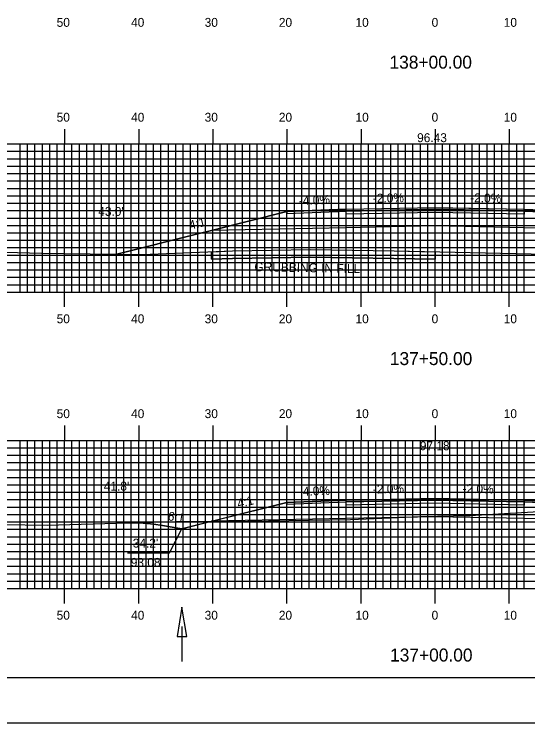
# Model space of a CAD drawing. Extents: x 1775564 to 1775907, y 442591 to 442811.
# Drawn here: x 1775672.9 to 1775742.2, y 442590.5 to 442686.2 of the extents above; entities that cross this region are included whole.
import ezdxf

# ---------------------------------------------------------------- set-up
doc = ezdxf.new("R2010")
doc.units = 0
for name, color, linetype in [('ANNOTATION', 7, 'Continuous'), ('BORDER', 7, 'Continuous'), ('D_Drainage_Ditch_Line', 7, 'Continuous'), ('D_Roadway_Centerline', 7, 'Continuous'), ('D_Roadway_Centerline_Text', 7, 'Continuous'), ('D_Roadway_Edge_Shoulder', 7, 'Continuous'), ('D_Roadway_Edge_TW', 7, 'Continuous'), ('D_Roadway_Pavement', 7, 'Continuous'), ('D_Roadway_SlopeLines', 7, 'Continuous'), ('D_Roadway_SubGrade', 7, 'Continuous'), ('D_Text_Standard', 7, 'Continuous'), ('GRUBBING IN FILL', 7, 'Continuous'), ('H_V ANNOTATION', 7, 'Continuous'), ('MAJOR', 7, 'Continuous'), ('MINOR', 7, 'Continuous'), ('PLOT BOUNDARY', 7, 'Continuous'), ('S_Roadway_Centerline', 7, 'Continuous')]:
    doc.layers.add(name, color=color, linetype=linetype)

msp = doc.modelspace()

# ---------------------------------------------------------------- linework, layer by layer
at = {"layer": 'ANNOTATION'}
msp.add_lwpolyline([(1775688.177, 442613.47), (1775693.869, 442613.47), (1775695.538, 442616.74)], dxfattribs=at)
at = {"layer": 'BORDER'}
msp.add_lwpolyline([(1775580.111, 442596.665), (1775900.111, 442596.665), (1775900.111, 442806.665), (1775580.111, 442806.665)], close=True, dxfattribs=at)
at = {"layer": 'D_Drainage_Ditch_Line'}
msp.add_line((1775695.538, 442603.524), (1775695.538, 442598.825), dxfattribs=at)
msp.add_lwpolyline([(1775694.882, 442602.211), (1775696.194, 442602.211), (1775695.538, 442606.148)], close=True, dxfattribs=at)
at = {"layer": 'D_Roadway_Centerline'}
for points in [[(1775686.739, 442653.791), (1775686.741, 442653.791), (1775697.711, 442656.534), (1775699.538, 442656.99), (1775705.211, 442658.409), (1775709.711, 442659.534), (1775717.712, 442659.854), (1775729.711, 442660.094), (1775731.768, 442660.053), (1775741.712, 442659.854), (1775747.545, 442659.621), (1775757.832, 442659.209), (1775757.833, 442659.209), (1775767.301, 442656.842), (1775774.243, 442655.106)], [(1775687.941, 442617.525), (1775688.446, 442617.526), (1775689.192, 442617.527), (1775690.297, 442617.476), (1775690.442, 442617.469), (1775691.691, 442617.351), (1775692.631, 442617.217), (1775692.942, 442617.173), (1775695.538, 442616.74), (1775699.537, 442617.74), (1775707.011, 442619.609), (1775709.711, 442620.284), (1775717.712, 442620.604), (1775722.433, 442620.699), (1775729.712, 442620.844), (1775739.526, 442620.648), (1775741.711, 442620.604), (1775753.997, 442620.112)]]:
    msp.add_lwpolyline(points, dxfattribs=at)
at = {"layer": 'D_Roadway_Edge_Shoulder'}
for points in [[(1775717.712, 442659.854), (1775709.711, 442659.534), (1775709.711, 442659.284), (1775717.712, 442659.604)], [(1775741.712, 442659.854), (1775757.833, 442659.209), (1775757.833, 442658.959), (1775741.712, 442659.604)], [(1775717.712, 442620.604), (1775709.711, 442620.284), (1775709.711, 442620.034), (1775717.712, 442620.354)], [(1775741.711, 442620.604), (1775753.997, 442620.112), (1775753.997, 442619.862), (1775741.711, 442620.354)]]:
    msp.add_lwpolyline(points, close=True, dxfattribs=at)
at = {"layer": 'D_Roadway_Edge_TW'}
for points in [[(1775717.712, 442659.604), (1775717.712, 442659.854), (1775729.711, 442660.094), (1775741.712, 442659.854), (1775741.712, 442659.604), (1775729.711, 442659.844)], [(1775717.712, 442620.354), (1775717.712, 442620.604), (1775729.712, 442620.844), (1775741.711, 442620.604), (1775741.711, 442620.354), (1775729.712, 442620.594)]]:
    msp.add_lwpolyline(points, close=True, dxfattribs=at)
at = {"layer": 'D_Roadway_Pavement'}
for points in [[(1775717.712, 442659.187), (1775717.712, 442659.604), (1775729.711, 442659.844), (1775741.712, 442659.604), (1775741.712, 442659.187), (1775729.711, 442659.427)], [(1775717.712, 442619.937), (1775717.712, 442620.354), (1775729.712, 442620.594), (1775741.711, 442620.354), (1775741.711, 442619.937), (1775729.712, 442620.177)]]:
    msp.add_lwpolyline(points, close=True, dxfattribs=at)
at = {"layer": 'D_Roadway_SlopeLines'}
for points in [[(1775709.711, 442659.534), (1775699.537, 442656.99), (1775697.711, 442656.534), (1775686.739, 442653.791)], [(1775709.711, 442620.284), (1775695.538, 442616.74)], [(1775695.538, 442616.74), (1775692.942, 442617.173), (1775691.692, 442617.351), (1775690.442, 442617.469), (1775689.192, 442617.527), (1775687.941, 442617.525)]]:
    msp.add_lwpolyline(points, dxfattribs=at)
at = {"layer": 'D_Roadway_SubGrade'}
for points in [[(1775717.712, 442657.354), (1775699.537, 442656.99), (1775709.711, 442659.534), (1775709.711, 442659.284), (1775717.712, 442659.604), (1775729.711, 442659.844), (1775741.712, 442659.604), (1775757.833, 442658.959), (1775757.833, 442659.209), (1775767.3, 442656.842), (1775741.712, 442657.354), (1775729.711, 442657.594)], [(1775717.712, 442618.104), (1775699.537, 442617.74), (1775709.711, 442620.284), (1775709.711, 442620.034), (1775717.712, 442620.354), (1775729.712, 442620.594), (1775741.711, 442620.354), (1775753.997, 442619.862), (1775753.997, 442620.112), (1775763.798, 442617.662), (1775741.711, 442618.104), (1775729.712, 442618.344)]]:
    msp.add_lwpolyline(points, close=True, dxfattribs=at)
at = {"layer": 'GRUBBING IN FILL'}
msp.add_lwpolyline([(1775699.537, 442653.105), (1775699.537, 442654.106), (1775702.35, 442654.215), (1775707.612, 442654.31), (1775712.875, 442654.405), (1775718.516, 442654.312), (1775724.158, 442654.219), (1775729.711, 442654.105), (1775729.711, 442653.105), (1775726.925, 442653.162), (1775724.14, 442653.22), (1775718.508, 442653.312), (1775712.876, 442653.405), (1775707.627, 442653.31), (1775702.378, 442653.215)], close=True, dxfattribs=at)
msp.add_lwpolyline([(1775699.537, 442653.105), (1775699.537, 442654.106), (1775702.35, 442654.215), (1775707.612, 442654.31), (1775712.875, 442654.405), (1775718.516, 442654.312), (1775724.158, 442654.219), (1775729.711, 442654.105), (1775729.711, 442653.105), (1775726.925, 442653.162), (1775724.14, 442653.22), (1775718.508, 442653.312), (1775712.876, 442653.405), (1775707.627, 442653.31), (1775702.378, 442653.215)], close=True, dxfattribs=at)
msp.add_lwpolyline([(1775699.537, 442653.105), (1775702.378, 442653.215), (1775712.876, 442653.405), (1775724.14, 442653.22), (1775729.711, 442653.105)], dxfattribs=at)
msp.add_lwpolyline([(1775699.537, 442653.105), (1775702.378, 442653.215), (1775712.876, 442653.405), (1775724.14, 442653.22), (1775729.711, 442653.105)], dxfattribs=at)
at = {"layer": 'MAJOR'}
for p, q in [((1775679.711, 442670.669), (1775679.711, 442668.665)), ((1775689.711, 442670.669), (1775689.711, 442668.665)), ((1775699.711, 442670.669), (1775699.711, 442668.665)), ((1775709.711, 442670.669), (1775709.711, 442668.665)), ((1775719.711, 442670.669), (1775719.711, 442668.665)), ((1775729.711, 442670.669), (1775729.711, 442668.665)), ((1775739.711, 442670.669), (1775739.711, 442668.665)), ((1775589.711, 442668.665), (1775869.711, 442668.665)), ((1775589.711, 442668.665), (1775869.711, 442668.665)), ((1775679.711, 442648.665), (1775679.711, 442668.665)), ((1775689.711, 442648.665), (1775689.711, 442668.665)), ((1775699.711, 442648.665), (1775699.711, 442668.665)), ((1775709.711, 442648.665), (1775709.711, 442668.665)), ((1775719.711, 442648.665), (1775719.711, 442668.665)), ((1775729.711, 442648.665), (1775729.711, 442668.665)), ((1775739.711, 442648.665), (1775739.711, 442668.665)), ((1775589.711, 442663.665), (1775869.711, 442663.665)), ((1775589.711, 442658.665), (1775869.711, 442658.665)), ((1775589.711, 442653.665), (1775869.711, 442653.665)), ((1775589.711, 442648.665), (1775869.711, 442648.665)), ((1775589.711, 442648.665), (1775869.711, 442648.665)), ((1775679.711, 442646.661), (1775679.711, 442648.665)), ((1775689.711, 442646.661), (1775689.711, 442648.665)), ((1775699.711, 442646.661), (1775699.711, 442648.665)), ((1775709.711, 442646.661), (1775709.711, 442648.665)), ((1775719.711, 442646.661), (1775719.711, 442648.665)), ((1775729.711, 442646.661), (1775729.711, 442648.665)), ((1775739.711, 442646.661), (1775739.711, 442648.665)), ((1775679.711, 442630.669), (1775679.711, 442628.665)), ((1775689.711, 442630.669), (1775689.711, 442628.665)), ((1775699.711, 442630.669), (1775699.711, 442628.665)), ((1775709.711, 442630.669), (1775709.711, 442628.665)), ((1775719.711, 442630.669), (1775719.711, 442628.665)), ((1775729.711, 442630.669), (1775729.711, 442628.665)), ((1775739.711, 442630.669), (1775739.711, 442628.665)), ((1775589.711, 442628.665), (1775869.711, 442628.665)), ((1775589.711, 442628.665), (1775869.711, 442628.665)), ((1775679.711, 442608.665), (1775679.711, 442628.665)), ((1775689.711, 442608.665), (1775689.711, 442628.665)), ((1775699.711, 442608.665), (1775699.711, 442628.665)), ((1775709.711, 442608.665), (1775709.711, 442628.665)), ((1775719.711, 442608.665), (1775719.711, 442628.665)), ((1775729.711, 442608.665), (1775729.711, 442628.665)), ((1775739.711, 442608.665), (1775739.711, 442628.665)), ((1775589.711, 442623.665), (1775869.711, 442623.665)), ((1775589.711, 442618.665), (1775869.711, 442618.665)), ((1775589.711, 442613.665), (1775869.711, 442613.665)), ((1775589.711, 442608.665), (1775869.711, 442608.665)), ((1775589.711, 442608.665), (1775869.711, 442608.665)), ((1775679.711, 442606.661), (1775679.711, 442608.665)), ((1775689.711, 442606.661), (1775689.711, 442608.665)), ((1775699.711, 442606.661), (1775699.711, 442608.665)), ((1775709.711, 442606.661), (1775709.711, 442608.665)), ((1775719.711, 442606.661), (1775719.711, 442608.665)), ((1775729.711, 442606.661), (1775729.711, 442608.665)), ((1775739.711, 442606.661), (1775739.711, 442608.665))]:
    msp.add_line(p, q, dxfattribs=at)
at = {"layer": 'MINOR'}
for p, q in [((1775673.711, 442648.665), (1775673.711, 442668.665)), ((1775674.711, 442648.665), (1775674.711, 442668.665)), ((1775675.711, 442648.665), (1775675.711, 442668.665)), ((1775676.711, 442648.665), (1775676.711, 442668.665)), ((1775677.711, 442648.665), (1775677.711, 442668.665)), ((1775678.711, 442648.665), (1775678.711, 442668.665)), ((1775680.711, 442648.665), (1775680.711, 442668.665)), ((1775681.711, 442648.665), (1775681.711, 442668.665)), ((1775682.711, 442648.665), (1775682.711, 442668.665)), ((1775683.711, 442648.665), (1775683.711, 442668.665)), ((1775684.711, 442648.665), (1775684.711, 442668.665)), ((1775685.711, 442648.665), (1775685.711, 442668.665)), ((1775686.711, 442648.665), (1775686.711, 442668.665)), ((1775687.711, 442648.665), (1775687.711, 442668.665)), ((1775688.711, 442648.665), (1775688.711, 442668.665)), ((1775690.711, 442648.665), (1775690.711, 442668.665)), ((1775691.711, 442648.665), (1775691.711, 442668.665)), ((1775692.711, 442648.665), (1775692.711, 442668.665)), ((1775693.711, 442648.665), (1775693.711, 442668.665)), ((1775694.711, 442648.665), (1775694.711, 442668.665)), ((1775695.711, 442648.665), (1775695.711, 442668.665)), ((1775696.711, 442648.665), (1775696.711, 442668.665)), ((1775697.711, 442648.665), (1775697.711, 442668.665)), ((1775698.711, 442648.665), (1775698.711, 442668.665)), ((1775700.711, 442648.665), (1775700.711, 442668.665)), ((1775701.711, 442648.665), (1775701.711, 442668.665)), ((1775702.711, 442648.665), (1775702.711, 442668.665)), ((1775703.711, 442648.665), (1775703.711, 442668.665)), ((1775704.711, 442648.665), (1775704.711, 442668.665)), ((1775705.711, 442648.665), (1775705.711, 442668.665)), ((1775706.711, 442648.665), (1775706.711, 442668.665)), ((1775707.711, 442648.665), (1775707.711, 442668.665)), ((1775708.711, 442648.665), (1775708.711, 442668.665)), ((1775710.711, 442648.665), (1775710.711, 442668.665)), ((1775711.711, 442648.665), (1775711.711, 442668.665)), ((1775712.711, 442648.665), (1775712.711, 442668.665)), ((1775713.711, 442648.665), (1775713.711, 442668.665)), ((1775714.711, 442648.665), (1775714.711, 442668.665)), ((1775715.711, 442648.665), (1775715.711, 442668.665)), ((1775716.711, 442648.665), (1775716.711, 442668.665)), ((1775717.711, 442648.665), (1775717.711, 442668.665)), ((1775718.711, 442648.665), (1775718.711, 442668.665)), ((1775720.711, 442648.665), (1775720.711, 442668.665)), ((1775721.711, 442648.665), (1775721.711, 442668.665)), ((1775722.711, 442648.665), (1775722.711, 442668.665)), ((1775723.711, 442648.665), (1775723.711, 442668.665)), ((1775724.711, 442648.665), (1775724.711, 442668.665)), ((1775725.711, 442648.665), (1775725.711, 442668.665)), ((1775726.711, 442648.665), (1775726.711, 442668.665)), ((1775727.711, 442648.665), (1775727.711, 442668.665)), ((1775728.711, 442648.665), (1775728.711, 442668.665)), ((1775730.711, 442648.665), (1775730.711, 442668.665)), ((1775731.711, 442648.665), (1775731.711, 442668.665)), ((1775732.711, 442648.665), (1775732.711, 442668.665)), ((1775733.711, 442648.665), (1775733.711, 442668.665)), ((1775734.711, 442648.665), (1775734.711, 442668.665)), ((1775735.711, 442648.665), (1775735.711, 442668.665)), ((1775736.711, 442648.665), (1775736.711, 442668.665)), ((1775737.711, 442648.665), (1775737.711, 442668.665)), ((1775738.711, 442648.665), (1775738.711, 442668.665)), ((1775740.711, 442648.665), (1775740.711, 442668.665)), ((1775741.711, 442648.665), (1775741.711, 442668.665)), ((1775589.711, 442667.665), (1775869.711, 442667.665)), ((1775589.711, 442666.665), (1775869.711, 442666.665)), ((1775589.711, 442665.665), (1775869.711, 442665.665)), ((1775589.711, 442664.665), (1775869.711, 442664.665)), ((1775589.711, 442662.665), (1775869.711, 442662.665)), ((1775589.711, 442661.665), (1775869.711, 442661.665)), ((1775589.711, 442660.665), (1775869.711, 442660.665)), ((1775589.711, 442659.665), (1775869.711, 442659.665)), ((1775589.711, 442657.665), (1775869.711, 442657.665)), ((1775589.711, 442656.665), (1775869.711, 442656.665)), ((1775589.711, 442655.665), (1775869.711, 442655.665)), ((1775589.711, 442654.665), (1775869.711, 442654.665)), ((1775589.711, 442652.665), (1775869.711, 442652.665)), ((1775589.711, 442651.665), (1775869.711, 442651.665)), ((1775589.711, 442650.665), (1775869.711, 442650.665)), ((1775589.711, 442649.665), (1775869.711, 442649.665)), ((1775673.711, 442608.665), (1775673.711, 442628.665)), ((1775674.711, 442608.665), (1775674.711, 442628.665)), ((1775675.711, 442608.665), (1775675.711, 442628.665)), ((1775676.711, 442608.665), (1775676.711, 442628.665)), ((1775677.711, 442608.665), (1775677.711, 442628.665)), ((1775678.711, 442608.665), (1775678.711, 442628.665)), ((1775680.711, 442608.665), (1775680.711, 442628.665)), ((1775681.711, 442608.665), (1775681.711, 442628.665)), ((1775682.711, 442608.665), (1775682.711, 442628.665)), ((1775683.711, 442608.665), (1775683.711, 442628.665)), ((1775684.711, 442608.665), (1775684.711, 442628.665)), ((1775685.711, 442608.665), (1775685.711, 442628.665)), ((1775686.711, 442608.665), (1775686.711, 442628.665)), ((1775687.711, 442608.665), (1775687.711, 442628.665)), ((1775688.711, 442608.665), (1775688.711, 442628.665)), ((1775690.711, 442608.665), (1775690.711, 442628.665)), ((1775691.711, 442608.665), (1775691.711, 442628.665)), ((1775692.711, 442608.665), (1775692.711, 442628.665)), ((1775693.711, 442608.665), (1775693.711, 442628.665)), ((1775694.711, 442608.665), (1775694.711, 442628.665)), ((1775695.711, 442608.665), (1775695.711, 442628.665)), ((1775696.711, 442608.665), (1775696.711, 442628.665)), ((1775697.711, 442608.665), (1775697.711, 442628.665)), ((1775698.711, 442608.665), (1775698.711, 442628.665)), ((1775700.711, 442608.665), (1775700.711, 442628.665)), ((1775701.711, 442608.665), (1775701.711, 442628.665)), ((1775702.711, 442608.665), (1775702.711, 442628.665)), ((1775703.711, 442608.665), (1775703.711, 442628.665)), ((1775704.711, 442608.665), (1775704.711, 442628.665)), ((1775705.711, 442608.665), (1775705.711, 442628.665)), ((1775706.711, 442608.665), (1775706.711, 442628.665)), ((1775707.711, 442608.665), (1775707.711, 442628.665)), ((1775708.711, 442608.665), (1775708.711, 442628.665)), ((1775710.711, 442608.665), (1775710.711, 442628.665)), ((1775711.711, 442608.665), (1775711.711, 442628.665)), ((1775712.711, 442608.665), (1775712.711, 442628.665)), ((1775713.711, 442608.665), (1775713.711, 442628.665)), ((1775714.711, 442608.665), (1775714.711, 442628.665)), ((1775715.711, 442608.665), (1775715.711, 442628.665)), ((1775716.711, 442608.665), (1775716.711, 442628.665)), ((1775717.711, 442608.665), (1775717.711, 442628.665)), ((1775718.711, 442608.665), (1775718.711, 442628.665)), ((1775720.711, 442608.665), (1775720.711, 442628.665)), ((1775721.711, 442608.665), (1775721.711, 442628.665)), ((1775722.711, 442608.665), (1775722.711, 442628.665)), ((1775723.711, 442608.665), (1775723.711, 442628.665)), ((1775724.711, 442608.665), (1775724.711, 442628.665)), ((1775725.711, 442608.665), (1775725.711, 442628.665)), ((1775726.711, 442608.665), (1775726.711, 442628.665)), ((1775727.711, 442608.665), (1775727.711, 442628.665)), ((1775728.711, 442608.665), (1775728.711, 442628.665)), ((1775730.711, 442608.665), (1775730.711, 442628.665)), ((1775731.711, 442608.665), (1775731.711, 442628.665)), ((1775732.711, 442608.665), (1775732.711, 442628.665)), ((1775733.711, 442608.665), (1775733.711, 442628.665)), ((1775734.711, 442608.665), (1775734.711, 442628.665)), ((1775735.711, 442608.665), (1775735.711, 442628.665)), ((1775736.711, 442608.665), (1775736.711, 442628.665)), ((1775737.711, 442608.665), (1775737.711, 442628.665)), ((1775738.711, 442608.665), (1775738.711, 442628.665)), ((1775740.711, 442608.665), (1775740.711, 442628.665)), ((1775741.711, 442608.665), (1775741.711, 442628.665)), ((1775589.711, 442627.665), (1775869.711, 442627.665)), ((1775589.711, 442626.665), (1775869.711, 442626.665)), ((1775589.711, 442625.665), (1775869.711, 442625.665)), ((1775589.711, 442624.665), (1775869.711, 442624.665)), ((1775589.711, 442622.665), (1775869.711, 442622.665)), ((1775589.711, 442621.665), (1775869.711, 442621.665)), ((1775589.711, 442620.665), (1775869.711, 442620.665)), ((1775589.711, 442619.665), (1775869.711, 442619.665)), ((1775589.711, 442617.665), (1775869.711, 442617.665)), ((1775589.711, 442616.665), (1775869.711, 442616.665)), ((1775589.711, 442615.665), (1775869.711, 442615.665)), ((1775589.711, 442614.665), (1775869.711, 442614.665)), ((1775589.711, 442612.665), (1775869.711, 442612.665)), ((1775589.711, 442611.665), (1775869.711, 442611.665)), ((1775589.711, 442610.665), (1775869.711, 442610.665)), ((1775589.711, 442609.665), (1775869.711, 442609.665))]:
    msp.add_line(p, q, dxfattribs=at)
at = {"layer": 'PLOT BOUNDARY'}
msp.add_lwpolyline([(1775563.925, 442590.547), (1775903.925, 442590.547), (1775903.925, 442810.547), (1775563.925, 442810.547)], close=True, dxfattribs=at)
at = {"layer": 'S_Roadway_Centerline'}
for points in [[(1775589.711, 442662.039), (1775594.765, 442661.38), (1775612.346, 442659.096), (1775618.323, 442658.42), (1775630.14, 442656.981), (1775635.497, 442656.385), (1775653.235, 442654.547), (1775657.034, 442654.452), (1775676.595, 442653.914), (1775679.687, 442653.892), (1775690.111, 442653.742), (1775702.35, 442654.215), (1775712.875, 442654.405), (1775724.158, 442654.219), (1775746.739, 442653.754), (1775747.04, 442653.746), (1775747.179, 442653.746), (1775747.308, 442653.754), (1775762.014, 442654.396), (1775778.331, 442655.344), (1775791.988, 442656.198)], [(1775671.367, 442617.314), (1775677.368, 442617.226), (1775681.932, 442617.369), (1775694.75, 442617.701), (1775704.446, 442617.76), (1775718.287, 442617.975), (1775727.836, 442618.408), (1775734.374, 442618.543), (1775742.951, 442619.027), (1775746.809, 442619.145), (1775750.001, 442619.229), (1775766.783, 442619.727), (1775769.905, 442619.679), (1775772.654, 442619.714), (1775789.917, 442620.057), (1775792.569, 442620.138)]]:
    msp.add_lwpolyline(points, dxfattribs=at)

# ---------------------------------------------------------------- texts
at = {"layer": 'ANNOTATION'}
for s, rotation, p in [('-4.0%', 2.29053, (1775711.343, 442660.401)), ('-2.0%', 1.14582, (1775721.317, 442660.727)), ('-2.0%', 358.85431, (1775734.426, 442660.8)), ('4:1', 14.03912, (1775696.663, 442657.079)), ('-4.0%', 2.29053, (1775711.343, 442621.151)), ('-2.0%', 1.14576, (1775721.318, 442621.477)), ('-2.0%', 358.85418, (1775733.397, 442621.571)), ('4:1', 14.03916, (1775703.16, 442619.508)), ('6:1', 350.52978, (1775693.573, 442617.896))]:
    msp.add_text(s, height=1.2, rotation=rotation, dxfattribs=at).set_placement(p)
for s, p in [("34.2'", (1775688.912, 442614.196)), ('93.08', (1775688.644, 442611.596))]:
    msp.add_text(s, height=1.2, dxfattribs=at).set_placement(p)
at = {"layer": 'D_Roadway_Centerline'}
for s, p in [('C', (1775729.706, 442660.094)), ('L', (1775729.711, 442660.087)), ('C', (1775729.706, 442620.844)), ('L', (1775729.712, 442620.837))]:
    msp.add_text(s, height=0.0146, dxfattribs=at).set_placement(p)
at = {"layer": 'D_Roadway_Centerline_Text'}
for s, p in [('96.43', (1775727.277, 442668.905)), ('97.18', (1775727.641, 442627.327))]:
    msp.add_text(s, height=1.2, dxfattribs=at).set_placement(p)
at = {"layer": 'D_Text_Standard'}
for s, p in [("43.0'", (1775684.25, 442658.959)), ("41.8'", (1775685.003, 442621.889))]:
    msp.add_text(s, height=1.2, dxfattribs=at).set_placement(p)
at = {"layer": 'GRUBBING IN FILL'}
msp.add_text('GRUBBING IN FILL', height=1.2, rotation=358.9728, dxfattribs=at).set_placement((1775705.316, 442651.488))
at = {"layer": 'H_V ANNOTATION'}
for s, height, p in [('50', 1.2, (1775678.641, 442684.465)), ('40', 1.2, (1775688.684, 442684.465)), ('30', 1.2, (1775698.609, 442684.465)), ('20', 1.2, (1775708.619, 442684.465)), ('10', 1.2, (1775718.962, 442684.465)), ('0', 1.2, (1775729.23, 442684.465)), ('10', 1.2, (1775738.962, 442684.465)), ('138+00.00', 1.75, (1775723.547, 442678.821)), ('50', 1.2, (1775678.641, 442671.665)), ('40', 1.2, (1775688.684, 442671.665)), ('30', 1.2, (1775698.609, 442671.665)), ('20', 1.2, (1775708.619, 442671.665)), ('10', 1.2, (1775718.962, 442671.665)), ('0', 1.2, (1775729.23, 442671.665)), ('10', 1.2, (1775738.962, 442671.665)), ('50', 1.2, (1775678.641, 442644.465)), ('40', 1.2, (1775688.684, 442644.465)), ('30', 1.2, (1775698.609, 442644.465)), ('20', 1.2, (1775708.619, 442644.465)), ('10', 1.2, (1775718.962, 442644.465)), ('0', 1.2, (1775729.23, 442644.465)), ('10', 1.2, (1775738.962, 442644.465)), ('137+50.00', 1.75, (1775723.594, 442638.821)), ('50', 1.2, (1775678.641, 442631.665)), ('40', 1.2, (1775688.684, 442631.665)), ('30', 1.2, (1775698.609, 442631.665)), ('20', 1.2, (1775708.619, 442631.665)), ('10', 1.2, (1775718.962, 442631.665)), ('0', 1.2, (1775729.23, 442631.665)), ('10', 1.2, (1775738.962, 442631.665)), ('50', 1.2, (1775678.641, 442604.465)), ('40', 1.2, (1775688.684, 442604.465)), ('30', 1.2, (1775698.609, 442604.465)), ('20', 1.2, (1775708.619, 442604.465)), ('10', 1.2, (1775718.962, 442604.465)), ('0', 1.2, (1775729.23, 442604.465)), ('10', 1.2, (1775738.962, 442604.465)), ('137+00.00', 1.75, (1775723.625, 442598.821))]:
    msp.add_text(s, height=height, dxfattribs=at).set_placement(p)

doc.saveas('drawing.dxf')
